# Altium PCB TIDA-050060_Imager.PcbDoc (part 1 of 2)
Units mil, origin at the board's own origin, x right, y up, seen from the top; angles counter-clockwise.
Board outline 989.05 x 988.04 mil, 6 copper layers (TOP, GND1, POWER1, INNER1, GND2, BOTTOM), stack 61.2 mil thick; 79 components, 47 nets, 342 pads, 154 vias.
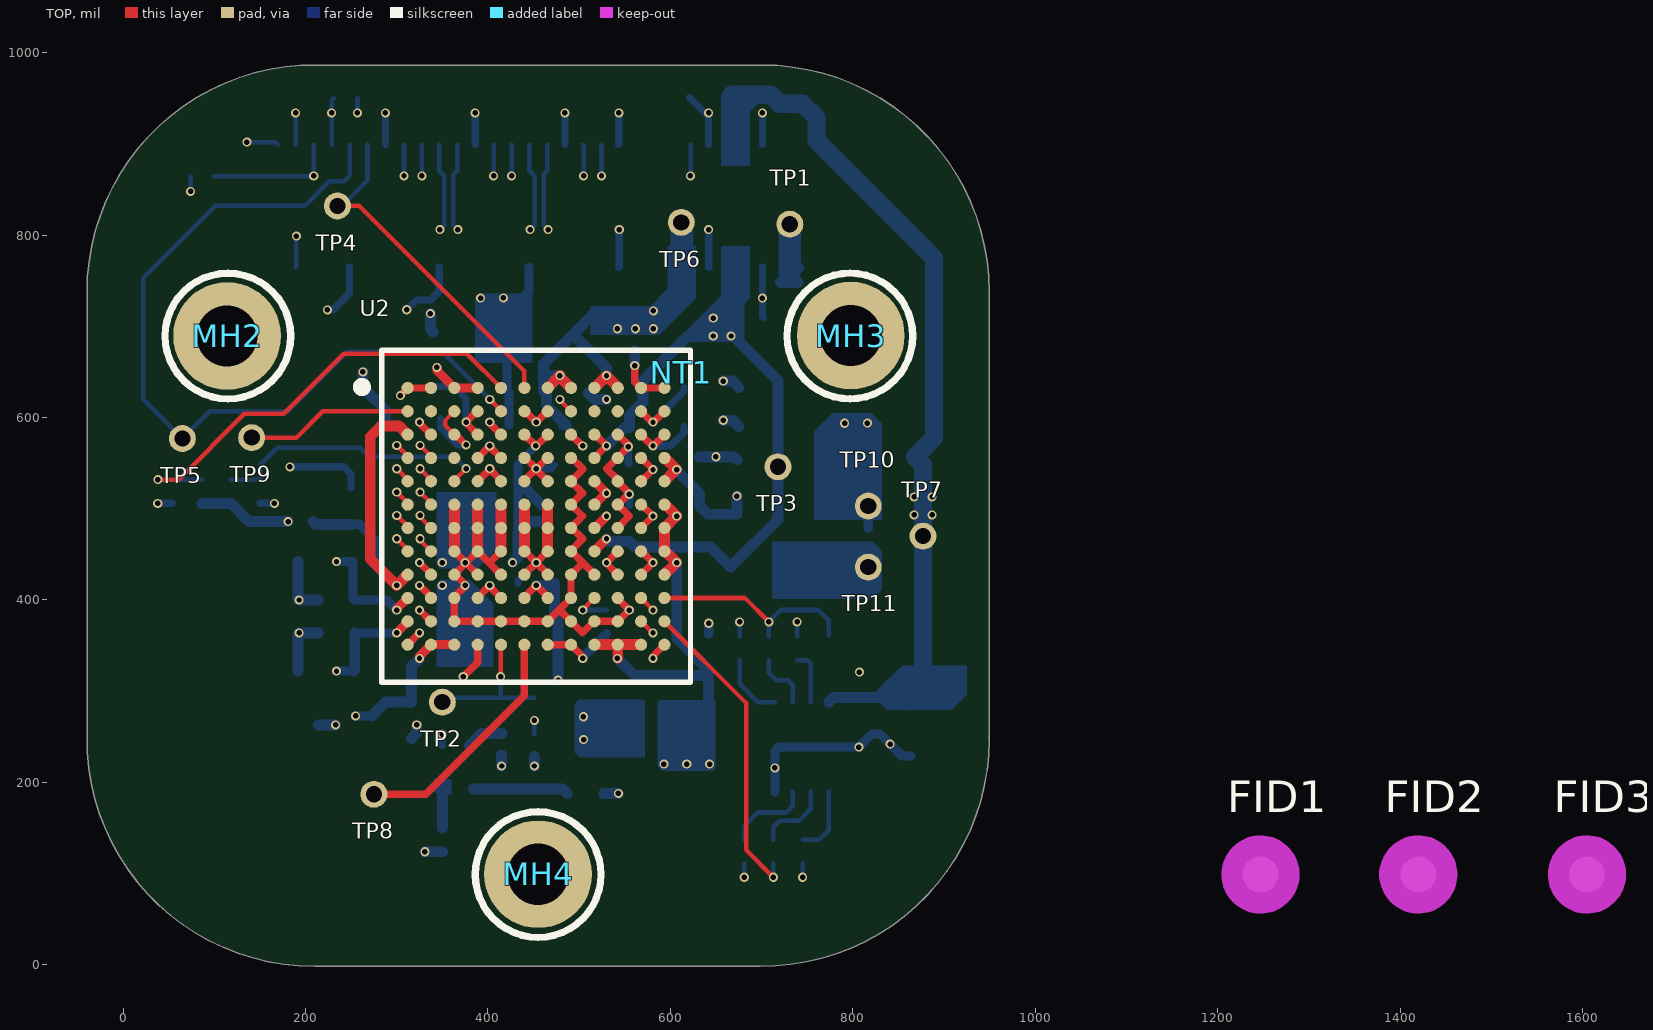
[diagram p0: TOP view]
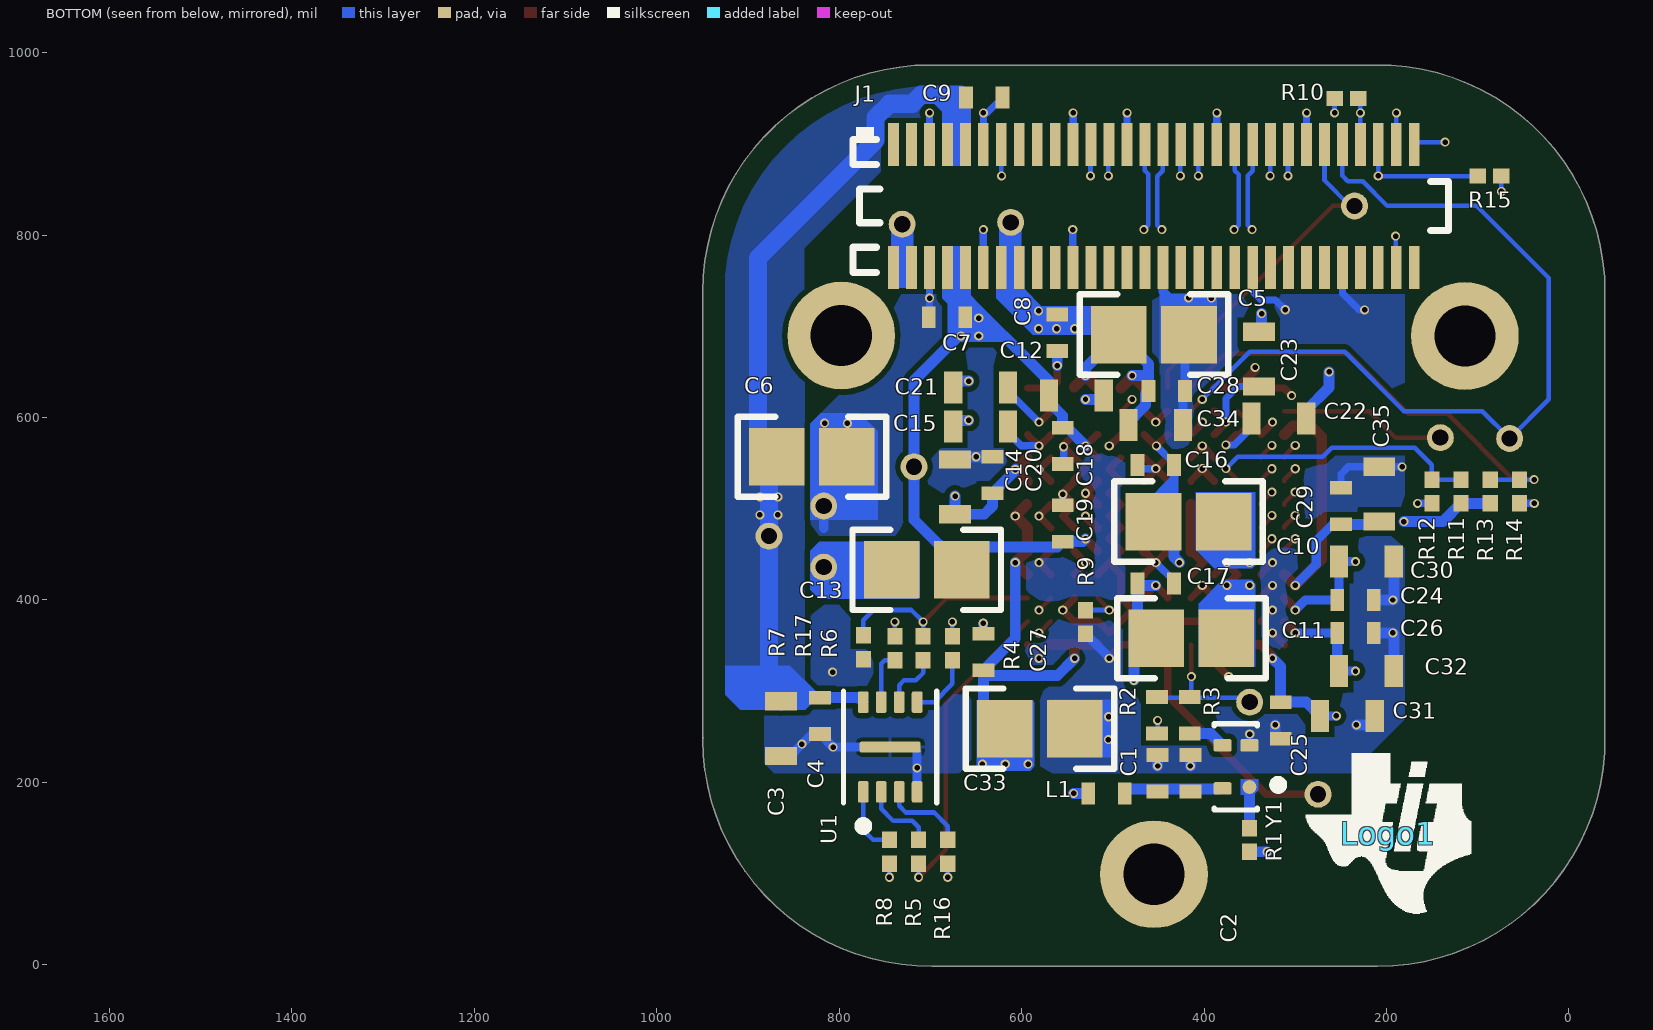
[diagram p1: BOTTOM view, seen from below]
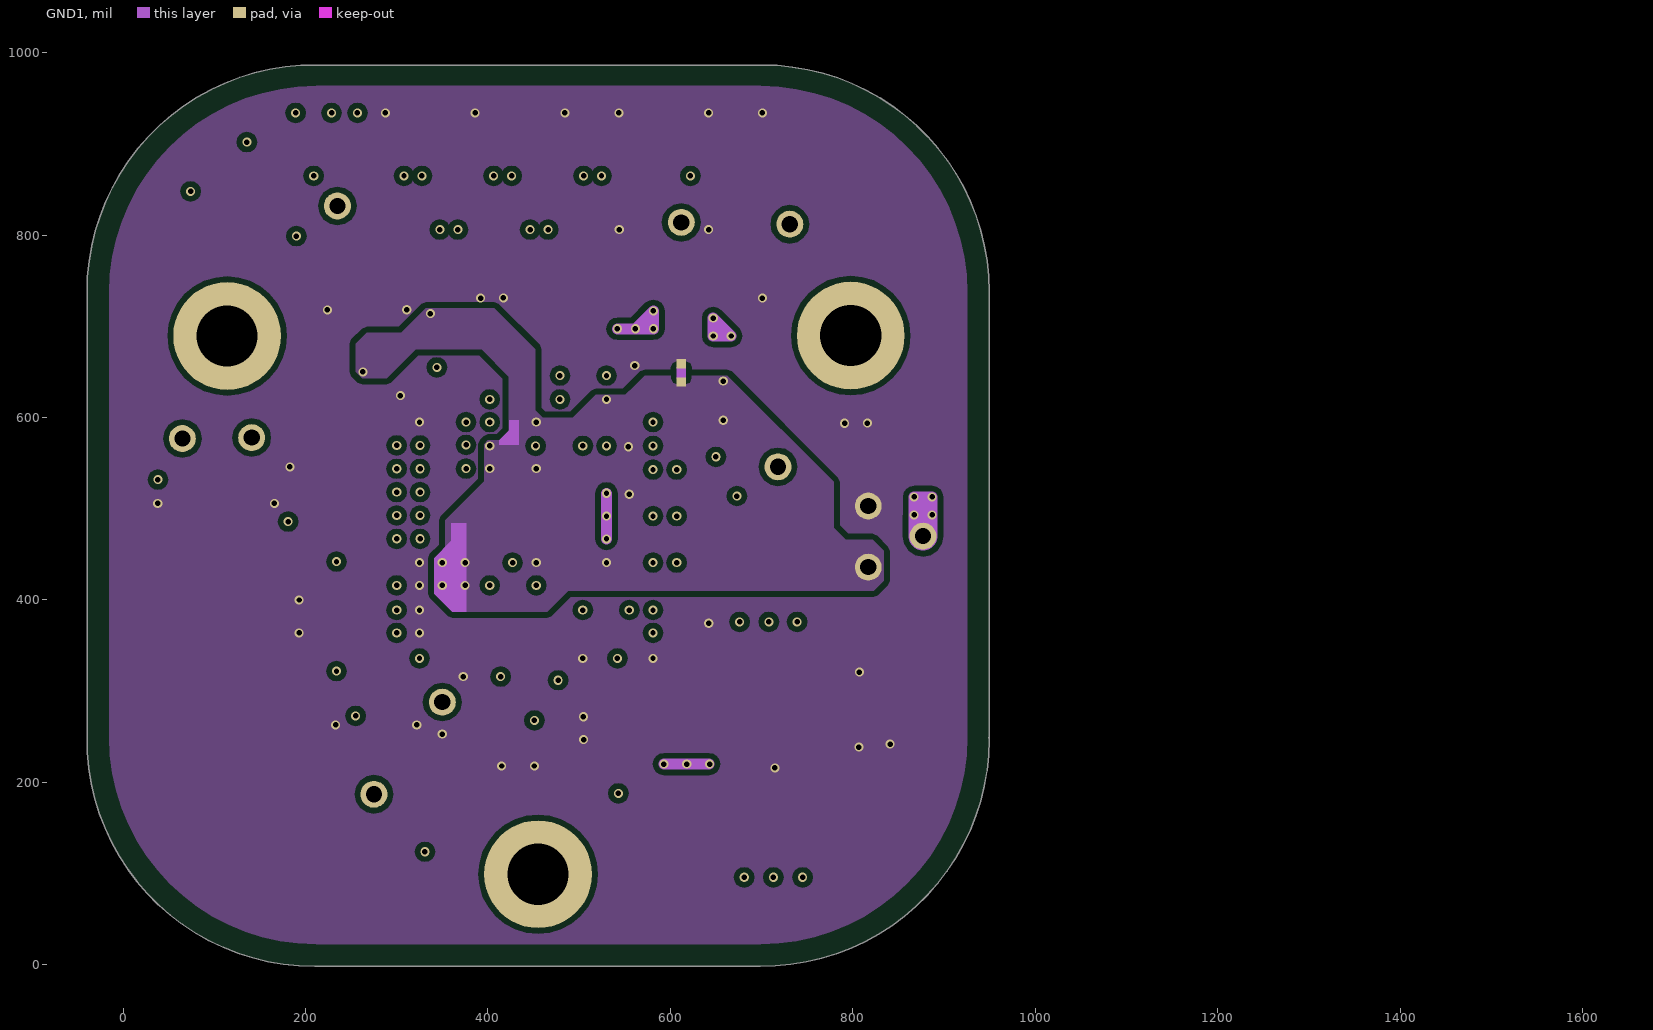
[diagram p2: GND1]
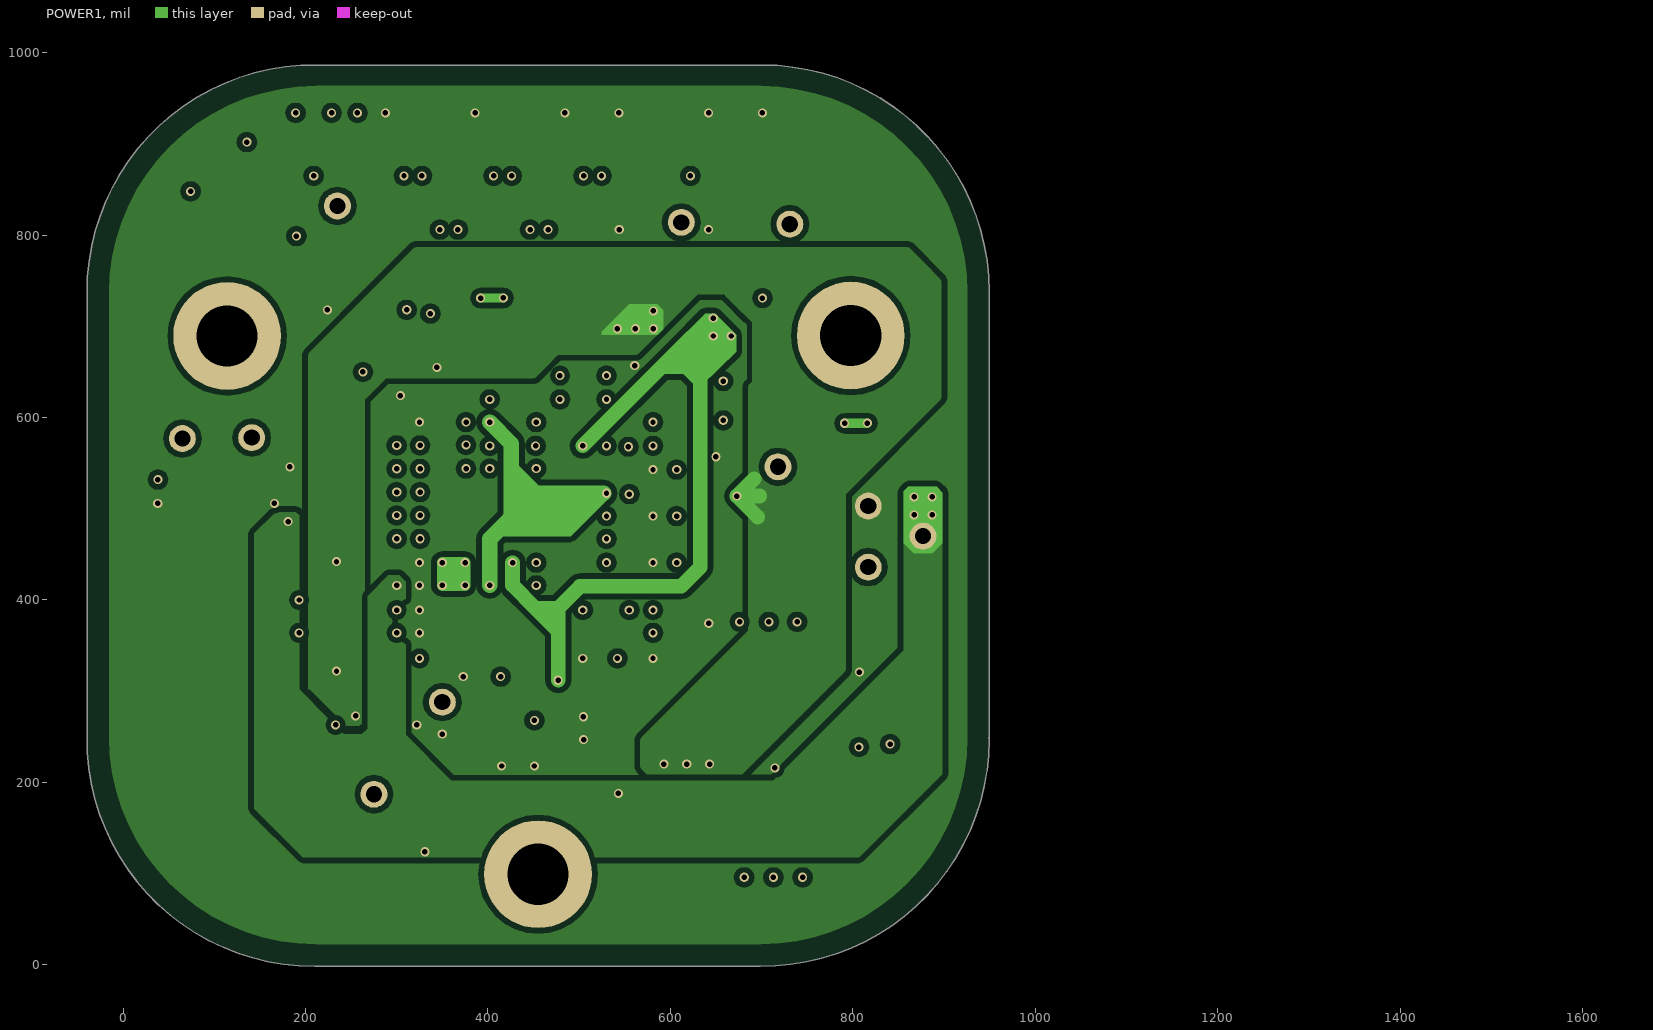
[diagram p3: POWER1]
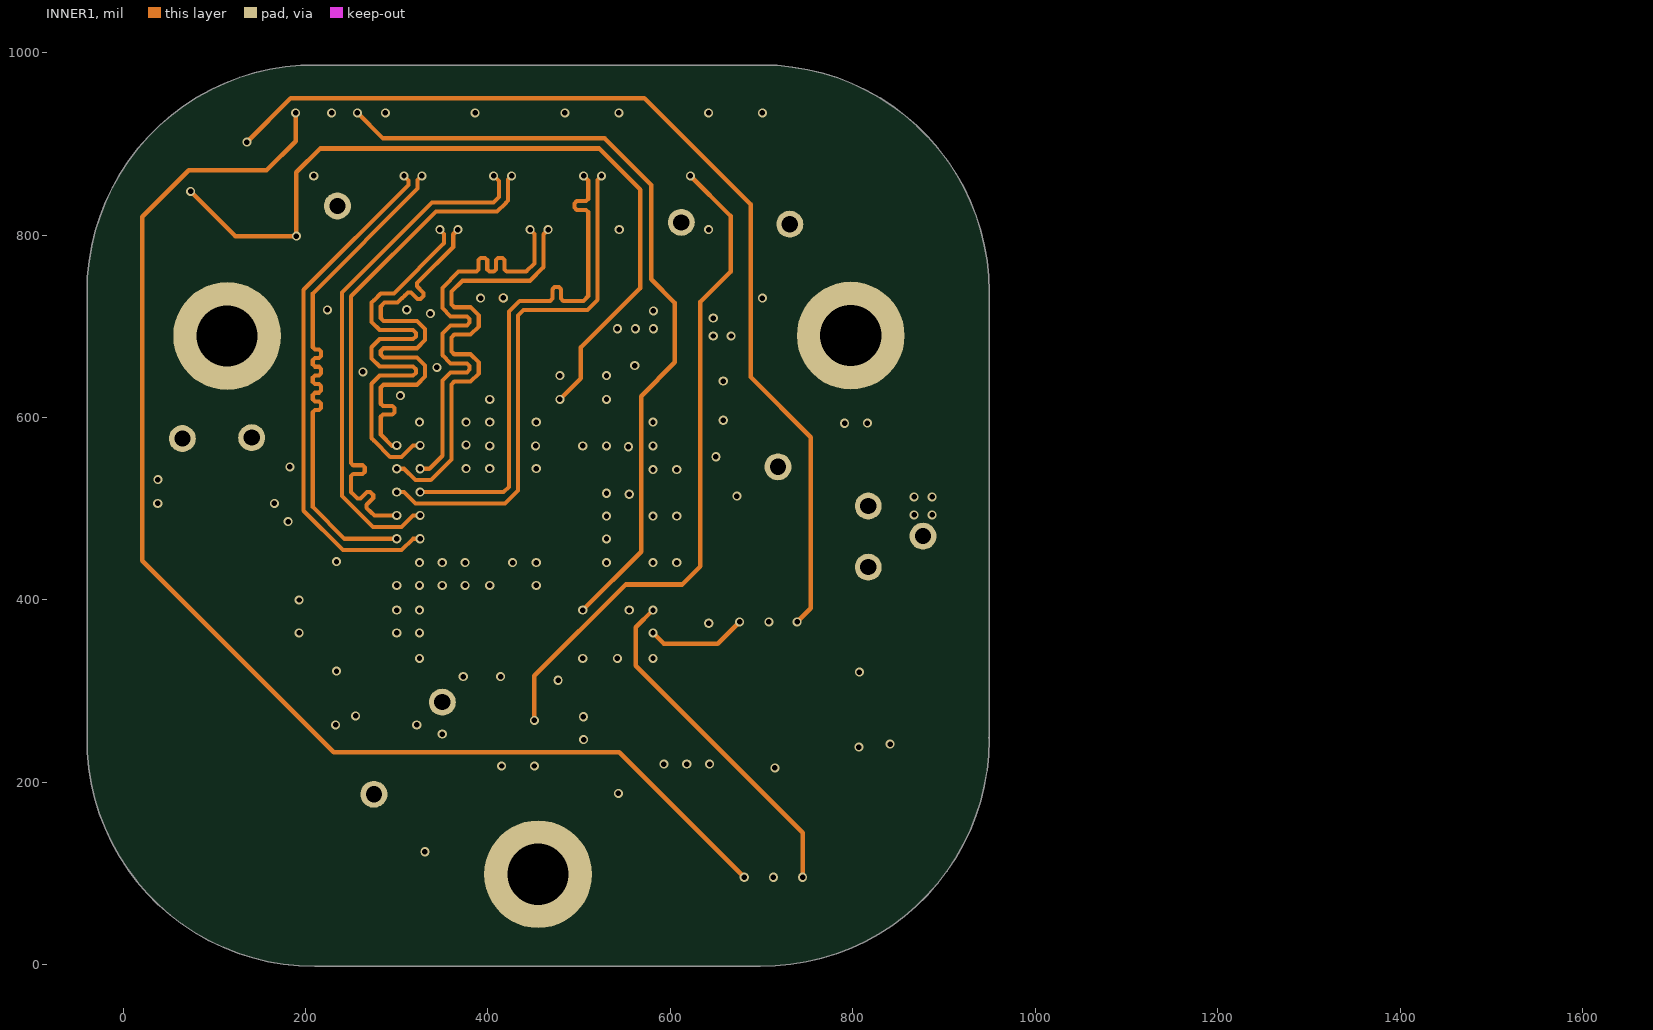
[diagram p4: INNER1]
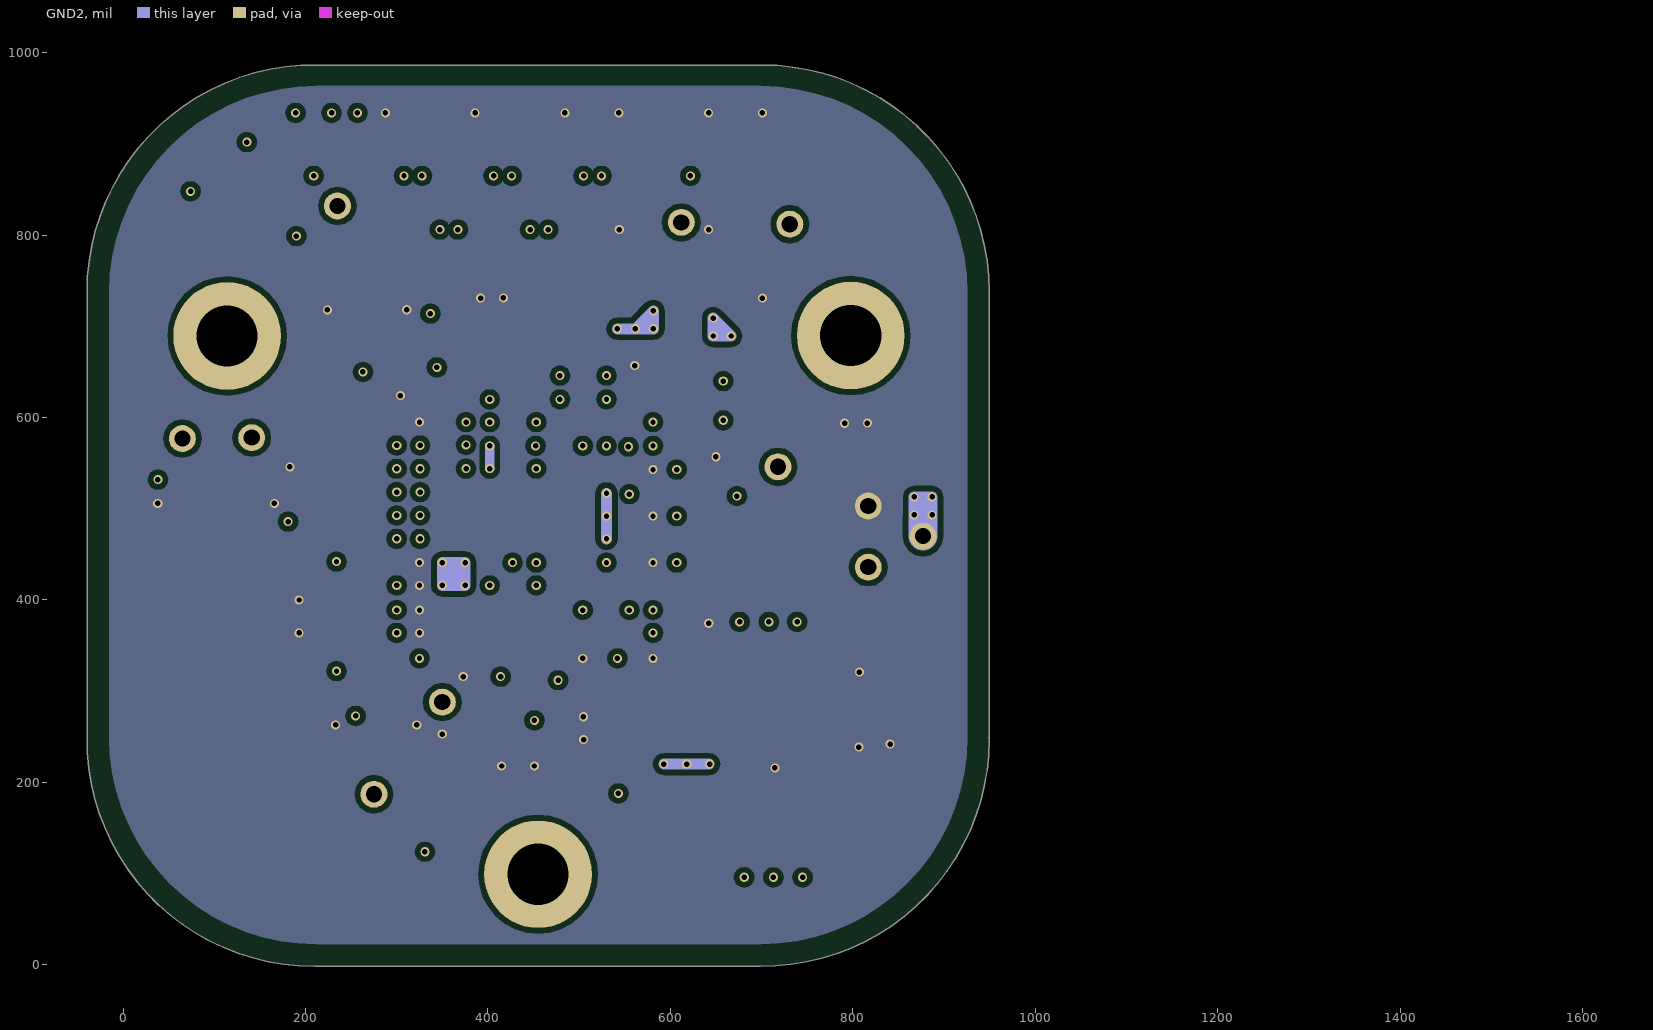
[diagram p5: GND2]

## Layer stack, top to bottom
Top Solder: solder mask 0.4, Solder Resist, Dk 3.5
TOP: signal copper 1.4
Dielectric 1: core 4, FR-4, Dk 4.3
GND1: signal copper 0.7
Dielectric2: core 6, FR-4, Dk 4.3
POWER1: signal copper 0.7
Dielectric3: core 35.6, FR-4, Dk 4.5
INNER1: signal copper 0.7
Dielectric4: core 6, FR-4, Dk 4.3
GND2: signal copper 0.7
Dielectric5: core 4, FR-4, Dk 4.3
BOTTOM: signal copper 1.4
Bottom Solder: solder mask 0.4, Solder Resist, Dk 3.5

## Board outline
210,-1.52 cw(c208.99,247) -39.51,250.01 cw(c208.99,247) -39.51,250.02 -39.51,250 -39.51,736.86 cw(c-38.01,737) -39.52,736.99 cw(c209,738) 211.85,986.51 cw(c212.01,985) 212.01,986.51 699.88,986.51 cw(c700.01,985.01) 700,986.52 cw(c701.01,738) 949.53,738 cw(c701.01,738) 949.52,734.99 949.52,250 cw(c948,250) 949.14,249 cw(c948.01,247.99) 949.52,248 cw(c701,246.99) 949.52,246.99 cw(c701,246.99) 697.99,-1.52 cw(c701,246.99) 697.98,-1.51 698,-1.52 210.12,-1.52 cw(c209.99,-0.01)

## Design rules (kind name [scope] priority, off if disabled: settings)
AcuteAngle [All] p1 off: minimum=4.50000000000000E+0001 checktracksonly=FALSE
AssemblyTestPointUsage [All] p1: valid=2
Clearance Clearance_BoardEdge_MountingHoles [OnCopper and InComponentClass('Mounting Holes') vs IsKeepOut] p1 off: gap=30 ignorepadtopadclearanceinfootprint=FALSE except(0: Arc-Hole Track-Hole SMDPad-Hole THPad-Hole Via-Hole Fill-Hole Poly-Hole Region-Hole Text-Hole)
Clearance Clearance_BoardEdge_Poly [OnCopper and InPoly vs IsKeepOut] p2: gap=15 ignorepadtopadclearanceinfootprint=FALSE except(0: Arc-Hole Track-Hole SMDPad-Hole THPad-Hole Via-Hole Fill-Hole Poly-Hole Region-Hole Text-Hole)
Clearance Clearance_BoardEdge [OnCopper and Not InComponentClass('Logo') and not InComponentClass('FiducialMark') and not InRegion(1000,500,4000,800) and Not IsKeepout vs IsKeepOut and Not OnLayer('Keep-out Layer')] p3: gap=11 ignorepadtopadclearanceinfootprint=FALSE except(0: Arc-Hole Track-Hole SMDPad-Hole THPad-Hole Via-Hole Fill-Hole Poly-Hole Region-Hole Text-Hole)
Clearance Clearance_Poly [InNamedPolygon('GND_L01_P099')] p4: gap=6 ignorepadtopadclearanceinfootprint=FALSE
Clearance Clearance_Poly_1 [InPolygon] p5: gap=6 ignorepadtopadclearanceinfootprint=FALSE
Clearance Clearance_1 [All] p6: gap=4 ignorepadtopadclearanceinfootprint=FALSE except(0: Arc-Hole Track-Hole SMDPad-Hole THPad-Hole Via-Hole Fill-Hole Poly-Hole Region-Hole Text-Hole)
ComponentClearance ComponentClearance_1 [issmtcomponent] p1: gap=0 collisioncheckmode=3 verticalgap=0 showdistances=FALSE
ComponentClearance ComponentClearance_Shunt [InComponentClass('Header') vs InComponentClass('Shunt')] p2: gap=0 collisioncheckmode=3 verticalgap=0 showdistances=FALSE
ComponentClearance ComponentClearance_Logo [InComponentClass('Logo')] p3: gap=0 collisioncheckmode=3 verticalgap=0 showdistances=FALSE
ComponentClearance ComponentClearance_ScrewToNut [(HasFootprint('NY PMS 440 0025 PH')) vs (HasFootprint('Keystone_1902C'))] p4: gap=5 collisioncheckmode=3 verticalgap=10 showdistances=FALSE
ComponentClearance ComponentClearance_MountingHoles [InComponentClass('Mounting Holes')] p5: gap=50 collisioncheckmode=3 verticalgap=50 showdistances=FALSE
ComponentClearance ComponentClearance_SmallPassives [HasFootprint('0201*') or HasFootprint('0402*') or HasFootprint('0508') or HasFootprint('0603*') or HasFootprint('0612') or HasFootprint('0805*') or HasFootprint('0815*') or HasFootprint('0830*') or HasFootprint('1206*') or HasFootprint('1210*') or HasFootprint('1808*') or HasFootprint('1812*') or HasFootprint('1825*') or HasFootprint('2010*') or HasFootprint('2220*') or HasFootprint('2225*') or HasFootprint('2512*') or HasFootprint('2728*') or HasFootprint('3518*') vs HasFootprint('0201*') or HasFootprint('0402*') or HasFootprint('0508') or HasFootprint('0603*') or HasFootprint('0612') or HasFootprint('0805*') or HasFootprint('0815*') or HasFootprint('0830*') or HasFootprint('1206*') or HasFootprint('1210*') or HasFootprint('1808*') or HasFootprint('1812*') or HasFootprint('1825*') or HasFootprint('2010*') or HasFootprint('2220*') or HasFootprint('2225*') or HasFootprint('2512*') or HasFootprint('2728*') or HasFootprint('3518*')] p6: gap=0 collisioncheckmode=3 verticalgap=0 showdistances=FALSE
ComponentClearance ComponentClearance_THtoSMT [IsThruComponent vs IsSMTComponent] p7: gap=0 collisioncheckmode=3 verticalgap=0 showdistances=FALSE
ComponentClearance ComponentClearance_THtoTH [IsThruComponent vs IsThruComponent] p8: gap=0 collisioncheckmode=3 verticalgap=0 showdistances=FALSE
ComponentClearance [All] p9: gap=0 collisioncheckmode=3 verticalgap=0 showdistances=FALSE
DiffPairsRouting DiffPair_Diff100_DiffPairsRouting [InDifferentialPairClass('Diff100')] p1: maxlimit=8 minlimit=5 mostfreqgap=8 toplayer_mingap=8 toplayer_minwidth=8 toplayer_maxwidth=8 toplayer_prefwidth=8 midlayer1_mingap=8 midlayer1_minwidth=8 midlayer1_maxwidth=8 midlayer1_prefwidth=8 midlayer2_mingap=8 midlayer2_minwidth=8 midlayer2_maxwidth=8 midlayer2_prefwidth=8 midlayer3_maxgap=5 midlayer3_prefgap=5 midlayer3_minwidth=4.5 midlayer3_maxwidth=5 midlayer3_prefwidth=5 midlayer4_maxgap=5 midlayer4_prefgap=5 midlayer4_minwidth=5 midlayer4_maxwidth=5 midlayer4_prefwidth=5 bottomlayer_mingap=8 bottomlayer_minwidth=8 bottomlayer_maxwidth=8 bottomlayer_prefwidth=8 maxuncoupledlength=500
DiffPairsRouting [All] p2: maxlimit=15 minlimit=5 mostfreqgap=8 toplayer_maxgap=5 toplayer_prefgap=5 toplayer_minwidth=5 toplayer_maxwidth=15 toplayer_prefwidth=8 midlayer1_maxgap=5 midlayer1_prefgap=5 midlayer1_minwidth=5 midlayer1_maxwidth=15 midlayer1_prefwidth=8 midlayer2_minwidth=3 midlayer2_maxwidth=10 midlayer2_prefwidth=5 midlayer3_maxgap=5 midlayer3_prefgap=5 midlayer3_minwidth=4.5 midlayer3_maxwidth=15 midlayer3_prefwidth=8 midlayer4_maxgap=5 midlayer4_prefgap=5 midlayer4_minwidth=5 midlayer4_maxwidth=15 midlayer4_prefwidth=8 bottomlayer_maxgap=5 bottomlayer_prefgap=5 bottomlayer_minwidth=5 bottomlayer_maxwidth=15 bottomlayer_prefwidth=8 maxuncoupledlength=1000
FabricationTestPointUsage TestPointUsage [All] p1: valid=2 allowmultiple=FALSE
FabricationTestpoint Testpoint [All] p1: side=3 testpointundercomponent=TRUE minsize=40 maxsize=100 preferedsize=60 minholesize=0 maxholesize=40 preferedholesize=32 testpointgrid=1 allowsidetop=TRUE allowsidebottom=TRUE usegrid=TRUE gridtolerance=0.01
FanoutControl Fanout_LCC [IsLCC] p1: bgadir=Out bgaviamode=Centered fanoutstyle=Auto fanoutdirection=Alternating viagrid=1 // Fanout_LCC (Default Rule)
FanoutControl Fanout_BGA [IsBGA] p2: bgadir=Out bgaviamode=Centered fanoutstyle=Auto fanoutdirection=Alternating viagrid=1 // Fanout_BGA (Default Rule)
FanoutControl Fanout_Default [All] p4: bgadir=Out bgaviamode=Centered fanoutstyle=Auto fanoutdirection=Alternating viagrid=1 // Fanout_Default (Default Rule)
FanoutControl Fanout_Small [(CompPinCount < 5)] p5: bgadir=Out bgaviamode=Centered fanoutstyle=Auto fanoutdirection=OutThenIn viagrid=1 // Fanout_Small (Default Rule)
HoleSize [All] p1: absolutevalues=TRUE maxlimit=280 minlimit=6 maxpercent=80.000 minpercent=20.000
MatchedLengths DiffPair_Diff100_MatchedLengths [InDifferentialPairClass('Diff100')] p1: tolerance=25 checknetsindiffpair=FALSE checkdiffpairvsdiffpair=TRUE checkxsignals=TRUE checkothers=TRUE
MinimumAnnularRing MinimumAnnularRing_ThermalPadVias [IsVia and InAnyComponent] p1: minimumring=5.91
MinimumAnnularRing [All] p2: minimumring=2
MinimumSolderMaskSliver MinimumSolderMaskSliver_Logo [InComponentClass('Logo') vs InComponentClass('Logo')] p1: minsoldermaskwidth=0.7
MinimumSolderMaskSliver [All] p2: minsoldermaskwidth=3.94
PlaneConnect [All] p1: planeconnectstyle=Relief reliefexpansion=10 reliefentries=4 reliefconductorwidth=10 reliefairgap=10
PolygonConnect PolygonConnect_1 [InComponent('U1')] p1: thpad.connectstyle=Relief thpad.reliefconductorwidth=4 thpad.reliefentries=4 thpad.polygonreliefangle="90 Angle" thpad.airgapwidth=4 smdpad.connectstyle=Relief smdpad.reliefconductorwidth=4 smdpad.reliefentries=4 smdpad.polygonreliefangle="90 Angle" smdpad.airgapwidth=4 via.connectstyle=Direct via.reliefconductorwidth=12 via.reliefentries=4 via.polygonreliefangle="90 Angle" via.airgapwidth=6
PolygonConnect PolygonConnect_2 [InComponent('U4')] p2: thpad.connectstyle=Relief thpad.reliefconductorwidth=4 thpad.reliefentries=4 thpad.polygonreliefangle="90 Angle" thpad.airgapwidth=4 smdpad.connectstyle=Relief smdpad.reliefconductorwidth=4 smdpad.reliefentries=4 smdpad.polygonreliefangle="90 Angle" smdpad.airgapwidth=4 via.connectstyle=Direct via.reliefconductorwidth=12 via.reliefentries=4 via.polygonreliefangle="90 Angle" via.airgapwidth=6
PolygonConnect [All] p3: connectstyle=Direct reliefconductorwidth=12 reliefentries=4 polygonreliefangle="90 Angle" airgapwidth=6
RoutingVias ThermalPadVias [IsVia and InAnyComponent] p1: holewidth=7.87 width=19.68 viastyle="Through Hole" minholewidth=7.87 minwidth=19.68 maxholewidth=12.99 maxwidth=23.62
RoutingVias [All] p2: holewidth=10 width=22 viastyle="Through Hole" minholewidth=6 minwidth=10 maxholewidth=40 maxwidth=65
SMDToCorner [All] p1: distance=25000
SilkToBoardRegionClearance [Not ((IsComment or IsDesignator) And (Hide <> 'False')) and not InRegion(1000,500,4000,800)] p1:
SilkToSilkClearance [All] p1: silktosilkclearance=0
SilkToSolderMaskClearance SilkscreenOverComponentPads [IsPad] p1: minsilkscreentomaskgap=0.2 clearancetoexposedcopper=TRUE
SolderMaskExpansion [All] p1: expansion=1 istentingtop=FALSE
Width [All] p1: maxlimit=100 minlimit=5 preferedwidth=10 minimp=50.000000 maximp=50.000000 favimp=50.000000 checkconnectedcopper=TRUE
15 further rules are at their usual default settings.

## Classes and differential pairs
component class TIDA-050060_Imager: C1 C2 C3 C4 C5 C6 C7 C8 C9 C10 C11 C12 C13 C14 C15 C16 C17 C18 C19 C20 C21 C22 C23 C24 C25 C26 C27 C28 C29 C30 C31 C32 C33 C34 C35 J1 L1 NT1 R1 R2 R3 R4 R5 R6 R7 R8 R9 R10 R11 R12 R13 R14 R15 R16 R17 TP1 TP2 TP3 TP4 TP5 TP6 TP7 TP8 TP9 TP10 TP11 U1 U2 Y1
component class Logo: Logo1
component class TIDA-050060_Hardware: FID1 FID2 FID3 Logo1 ZZ1 ZZ2 ZZ3
component class FiducialMark: FID1 FID2 FID3
component class AssemblyNote: ZZ1 ZZ2 ZZ3
differential pair CSI2_D3: +CSI2_D3_P -CSI2_D3_N
differential pair CSI2_D2: +CSI2_D2_P -CSI2_D2_N
differential pair CSI2_D1: +CSI2_D1_P -CSI2_D1_N
differential pair CSI2_D0: +CSI2_D0_P -CSI2_D0_N
differential pair CSI2_CK: +CSI2_CK_P -CSI2_CK_N

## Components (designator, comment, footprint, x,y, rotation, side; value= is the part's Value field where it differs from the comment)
C1 "GCM155R71C104KA55D" 0402S 451,210 r90 bottom value=0.1uF
C2 "CGA2B3X7R1H103K050BB" 0402S 415,210 r90 bottom value=0.01uF
C3 "GCM188R71C105KA64J" 0603S 864,259 r270 bottom value=1uF
C4 "GCM155R71C104KA55D" 0402S 821,273 r270 bottom value=0.1uF
C5 "GCM21BR71A106KE22L" 0805M 455,691 r180 bottom value=10uF
C6 "GCM21BR71A106KE22L" 0805M 830,557 r180 bottom value=10uF
C7 "GCM155R71C104KA55D" 0402S 682,710 r0 bottom value=0.1uF
C8 "GCM155R71C104KA55D" 0402S 561,693 r270 bottom value=0.1uF
C9 "GCM155R71C104KA55D" 0402S 641,951 r180 bottom value=0.1uF
C10 "CGA4J3X7R1C475K125AE" 0805M 417,486 r180 bottom value=4.7uF
C11 "CGA4J3X7R1C475K125AE" 0805M 414,358 r180 bottom value=4.7uF
C12 "GCM188R71C105KA64J" 0603S 540,624 r180 bottom value=1uF
C13 "CGA4J3X7R1C475K125AE" 0805M 704,433 r0 bottom value=4.7uF
C14 "GCM188R71C105KA64J" 0603S 673,524 r90 bottom value=1uF
C15 "GCM188R70J225KE22D" 0603S 645,590 r0 bottom value=2.2uF
C16 "GCM155R71C104KA55D" 0402S 453,548 r0 bottom value=0.1uF
C17 "GCM155R71C104KA55D" 0402S 453,418 r180 bottom value=0.1uF
C18 "GCM155R71C104KA55D" 0402S 555,569 r270 bottom value=0.1uF
C19 "GCM155R71C104KA55D" 0402S 555,484 r90 bottom value=0.1uF
C20 "GCM155R71C104KA55D" 0402S 632,537 r90 bottom value=0.1uF
C21 "GCM188R70J225KE22D" 0603S 645,633 r0 bottom value=2.2uF
C22 "GCM188R71C105KA64J" 0603S 318,599 r180 bottom value=1uF
C23 "GCM188R71C105KA64J" 0603S 340,664 r90 bottom value=1uF
C24 "GCM155R71C104KA55D" 0402S 234,400 r180 bottom value=0.1uF
C25 "GCM155R71C104KA55D" 0402S 316,268 r270 bottom value=0.1uF
C26 "GCM155R71C104KA55D" 0402S 234,364 r180 bottom value=0.1uF
C27 "GCM155R71C104KA55D" 0402S 642,343 r90 bottom value=0.1uF
C28 "GCM155R71C104KA55D" 0402S 441,629 r180 bottom value=0.1uF
C29 "GCM155R71C104KA55D" 0402S 250,503 r90 bottom value=0.1uF
C30 "GCM188R71C105KA64J" 0603S 222,442 r180 bottom value=1uF
C31 "GCM188R71C105KA64J" 0603S 243,273 r180 bottom value=1uF
C32 "GCM188R71C105KA64J" 0603S 222,322 r180 bottom value=1uF
C33 "CGA4J3X7R1C475K125AE" 0805M 580,259 r180 bottom value=4.7uF
C34 "GCM188R71C105KA64J" 0603S 453,592 r180 bottom value=1uF
C35 "GCM188R71C105KA64J" 0603S 208,516 r90 bottom value=1uF
FID1 "Fiducial" Fiducial10-20 1247,99 r0 top
FID2 "Fiducial" Fiducial10-20 1420,99 r0 top
FID3 "Fiducial" Fiducial10-20 1605,99 r0 top
J1 "ST5-30-1.50-L-D-P-TR" Samtec_ST5-30-1_50-x-D-P 455,832 r180 bottom
L1 "BLM15AG221SN1D" 0402S 507,188 r180 bottom value="220 ohm"
Logo1 "Texas Instruments" TI_Symbol_Overlay_Small 198,144 r180 bottom
MH2 "MOUNT_HOLE_1_MTG170_300_MOUNT H" MTG170_300#1 115,689.37 r0 top
MH3 "MOUNT_HOLE_1_MTG170_300_MOUNT H" MTG170_300#2 796.9,689.44 r0 top
MH4 "MOUNT_HOLE_1_MTG170_300_MOUNT H" MTG170_300#3 455,99 r0 top
NT1 "Net-Tie" Net-Tie_10mil 612,649 r270 top net-tie
R1 "RC0201JR-074K7L" 0201 350,137 r270 bottom value=4.7k
R2 "ERJ-2GE0R00X" 0402S 451.71,273.64 r90 bottom value=0
R3 "ERJ-2GEJ220X" 0402S 415.71,273.64 r90 bottom value=22
R4 "ERJ-1GE0R00C" 0201 676,347.01 r90 bottom value=0
R5 "ERJ-1GE0R00C" 0201 713,124.01 r270 bottom value=0
R6 "ERJ-1GE0R00C" 0201 708,347.01 r90 bottom value=0
R7 "RC0201JR-074K7L" 0201 773.5,348.24 r90 bottom value=4.7k
R8 "ERJ-1GE0R00C" 0201 745,124.01 r90 bottom value=0
R9 "RC0201JR-074K7L" 0201 530,376 r90 bottom value=4.7k
R10 "ERJ-1GE0R00C" 0201 244,950 r180 bottom value=0
R11 "RC0201JR-074K7L" 0201 118.25,519.01 r270 bottom value=4.7k
R12 "RC0201JR-074K7L" 0201 150.25,519.01 r90 bottom value=4.7k
R13 "RC0201JR-074K7L" 0201 86.25,518.99 r270 bottom value=4.7k
R14 "RC0201JR-074K7L" 0201 54.25,518.99 r90 bottom value=4.7k
R15 "ERJ-1GE0R00C" 0201 87,864.7 r180 bottom value=0
R16 "ERJ-1GE0R00C" 0201 681,124.01 r90 bottom value=0
R17 "ERJ-1GE0R00C" 0201 739,347.01 r270 bottom value=0
TP1 "TP_H0.45P0.75" TP_H045P075 731,812 r180 top
TP2 "TP_H0.45P0.75" TP_H045P075 350,288 r90 top
TP3 "TP_H0.45P0.75" TP_H045P075 718,546 r180 top
TP4 "TP_H0.45P0.75" TP_H045P075 235,832 r90 top
TP5 "TP_H0.45P0.75" TP_H045P075 65,577 r90 top
TP6 "TP_H0.45P0.75" TP_H045P075 612,814 r180 top
TP7 "TP_H0.45P0.75" TP_H045P075 877,470 r180 top
TP8 "TP_H0.45P0.75" TP_H045P075 275,187 r90 top
TP9 "TP_H0.45P0.75" TP_H045P075 141,578 r90 top
TP10 "TP_H0.45P0.75" TP_H045P075 817,503 r90 top
TP11 "TP_H0.45P0.75" TP_H045P075 817,436 r90 top
U1 "W25Q40EWUXJE" FP-W25Q40EWUXJE_USON8-MFG 744.16,238.79 r90 bottom
U2 "IMX623-AAQV-W" FP-IMX623-AAQV-W_BGA144-IPC_C 452.76,491.76 r0 top
Y1 "DSC6101HA3B-024.0000" FP-DSC6101HA3B-024.0000_VFLGA4-MFG 365,217 r90 bottom
ZZ1 "These assemblies are ESD sensitive, ESD precautions shall be observed." AssemblyNote 185,3829.11 r180 bottom
ZZ2 "These assemblies must be clean and free from flux and all contaminants. Use of no clean flux is not acceptable." AssemblyNote 185,3740.56 r180 bottom
ZZ3 "These assemblies must comply with workmanship standards IPC-A-610 Class 2, unless otherwise specified." AssemblyNote 185,3652 r180 bottom

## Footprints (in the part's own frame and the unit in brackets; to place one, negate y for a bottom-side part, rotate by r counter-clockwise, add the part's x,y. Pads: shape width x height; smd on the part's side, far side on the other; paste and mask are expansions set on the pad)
0201 [mm] "Data from Kemet datasheet CC101_COM dated 7/28/11"
  rect 0.46x0.42 smd mask+0.048: 1(-0.33,0) 2(0.33,0)
  body extent -0.31,-0.16 0.31,0.16, height 0.26
0402S [mil] "Based on C0402S footprint from PADS legacy"
  rect 15x24 smd: 1(-20,0) 2(20,0)
  body extent -22,-12 22,12, height 24
0603S [mil]
  rect 20x35 smd: 1(-30,0) 2(30,0)
  body extent -34,-19 34,19, height 39
0805M [mm] "0805 from SM-752 data"
  rect 1.55x1.6 smd: 1(-0.975,0) 2(0.975,0)
  silkscreen extent -2.07,-1.12 2.07,1.12, body extent -1.1,-0.72 1.1,0.72, height 1.45
AssemblyNote [mil] "Assembly Note"
Fiducial10-20 [mm]
  round 1 smd mask+0.5: 1(0,0)
  TOP keep-out circle w1.178: c0,0 r0.5
FP-DSC6101HA3B-024.0000_VFLGA4-MFG [mm]
  round 0.387 smd paste+0 mask+0: 1(-0.56,-0.375)
  rrect29% 0.35x0.5 smd paste+0 mask+0: 2(0.6,-0.375) 3(0.6,0.375) 4(-0.6,0.375)
  TOP region: -0.775,-0.125 -0.345,-0.125 -0.345,-0.625 -0.645,-0.625 -0.775,-0.495
  silkscreen extent -1.2,-1.3 1.2,0.6, body extent -0.8,-0.6 0.8,0.6, height 0.89
FP-IMX623-AAQV-W_BGA144-IPC_C [mm]
  round 0.34 smd paste+0 mask+0: A1(-3.575,3.575) A2(-2.925,3.575) A3(-2.275,3.575) A4(-1.625,3.575) A5(-0.975,3.575) A6(-0.325,3.575) A7(0.325,3.575) A8(0.975,3.575) A9(1.625,3.575) A10(2.275,3.575) A11(2.925,3.575) A12(3.575,3.575) B1(-3.575,2.925) B2(-2.925,2.925) B3(-2.275,2.925) B4(-1.625,2.925) B5(-0.975,2.925) B6(-0.325,2.925) B7(0.325,2.925) B8(0.975,2.925) B9(1.625,2.925) B10(2.275,2.925) B11(2.925,2.925) B12(3.575,2.925) C1(-3.575,2.275) C2(-2.925,2.275) C3(-2.275,2.275) C4(-1.625,2.275) C5(-0.975,2.275) C6(-0.325,2.275) C7(0.325,2.275) C8(0.975,2.275) C9(1.625,2.275) C10(2.275,2.275) C11(2.925,2.275) C12(3.575,2.275) D1(-3.575,1.625) D2(-2.925,1.625) D3(-2.275,1.625) D4(-1.625,1.625) D5(-0.975,1.625) D6(-0.325,1.625) D7(0.325,1.625) D8(0.975,1.625) D9(1.625,1.625) D10(2.275,1.625) D11(2.925,1.625) D12(3.575,1.625) E1(-3.575,0.975) E2(-2.925,0.975) E3(-2.275,0.975) E4(-1.625,0.975) E5(-0.975,0.975) E6(-0.325,0.975) E7(0.325,0.975) E8(0.975,0.975) E9(1.625,0.975) E10(2.275,0.975) E11(2.925,0.975) E12(3.575,0.975) F1(-3.575,0.325) F2(-2.925,0.325) F3(-2.275,0.325) F4(-1.625,0.325) F5(-0.975,0.325) F6(-0.325,0.325) F7(0.325,0.325) F8(0.975,0.325) F9(1.625,0.325) F10(2.275,0.325) F11(2.925,0.325) F12(3.575,0.325) G1(-3.575,-0.325) G2(-2.925,-0.325) G3(-2.275,-0.325) G4(-1.625,-0.325) G5(-0.975,-0.325) G6(-0.325,-0.325) G7(0.325,-0.325) G8(0.975,-0.325) G9(1.625,-0.325) G10(2.275,-0.325) G11(2.925,-0.325) G12(3.575,-0.325) H1(-3.575,-0.975) H2(-2.925,-0.975) H3(-2.275,-0.975) H4(-1.625,-0.975) H5(-0.975,-0.975) H6(-0.325,-0.975) H7(0.325,-0.975) H8(0.975,-0.975) H9(1.625,-0.975) H10(2.275,-0.975) H11(2.925,-0.975) H12(3.575,-0.975) J1(-3.575,-1.625) J2(-2.925,-1.625) J3(-2.275,-1.625) J4(-1.625,-1.625) J5(-0.975,-1.625) J6(-0.325,-1.625) J7(0.325,-1.625) J8(0.975,-1.625) J9(1.625,-1.625) J10(2.275,-1.625) J11(2.925,-1.625) J12(3.575,-1.625) K1(-3.575,-2.275) K2(-2.925,-2.275) K3(-2.275,-2.275) K4(-1.625,-2.275) K5(-0.975,-2.275) K6(-0.325,-2.275) K7(0.325,-2.275) K8(0.975,-2.275) K9(1.625,-2.275) K10(2.275,-2.275) K11(2.925,-2.275) K12(3.575,-2.275) L1(-3.575,-2.925) L2(-2.925,-2.925) L3(-2.275,-2.925) L4(-1.625,-2.925) L5(-0.975,-2.925) L6(-0.325,-2.925) L7(0.325,-2.925) L8(0.975,-2.925) L9(1.625,-2.925) L10(2.275,-2.925) L11(2.925,-2.925) L12(3.575,-2.925) M1(-3.575,-3.575) M2(-2.925,-3.575) M3(-2.275,-3.575) M4(-1.625,-3.575) M5(-0.975,-3.575) M6(-0.325,-3.575) M7(0.325,-3.575) M8(0.975,-3.575) M9(1.625,-3.575) M10(2.275,-3.575) M11(2.925,-3.575) M12(3.575,-3.575)
  silkscreen extent -4.97,-4.62 4.3,4.62, body extent -4.4,-4.72 4.4,4.72, height 0.25
FP-W25Q40EWUXJE_USON8-MFG [mm]
  rrect33% 0.6x0.3 smd paste-1000 mask-1000: 1(-1.25,0.75) 2(-1.25,0.25) 3(-1.25,-0.25) 4(-1.25,-0.75) 5(1.25,-0.75) 6(1.25,-0.25) 7(1.25,0.25) 8(1.25,0.75)
  rrect33% 0.3x1.7 smd paste-1000 mask+0: 9(0,0)
  silkscreen extent -2.32,-1.3 1.55,1.3, body extent -1.5,-1 1.5,1, height 0.6
MTG170_300#1 [mm] "MTG170_300"
  round 3 hole 1.7: 1(-0.023,0.002)
  silkscreen extent -1.75,-1.75 1.75,1.75, body extent -1.76,-1.76 1.76,1.76, height 3.81
MTG170_300#2 [mm] "MTG170_300"
  round 3 hole 1.7: 1(0.023,0.011)
  silkscreen extent -1.75,-1.75 1.75,1.75, body extent -1.76,-1.76 1.76,1.76, height 3.81
MTG170_300#3 [mm] "MTG170_300"
  round 3 hole 1.7: 1(0,0.009)
  silkscreen extent -1.75,-1.75 1.75,1.75, body extent -1.76,-1.76 1.76,1.76, height 3.81
Net-Tie_10mil [mil] "10mil net tie, no solder mask opening, no solder paste"
  rect 10x10 on Mid1 paste-5 mask-5: 1(-10,0) 2(10,0)
  GND1 region: -6,5 6,5 6,-5 -6,-5
Samtec_ST5-30-1_50-x-D-P [mm] "Header(unshrouded), 0.5mm, 30x2, Tin, SMT"
  rect 0.3x1.2 smd: 1(-7.25,1.71) 2(-7.25,-1.71) 3(-6.75,1.71) 4(-6.75,-1.71) 5(-6.25,1.71) 6(-6.25,-1.71) 7(-5.75,1.71) 8(-5.75,-1.71) 9(-5.25,1.71) 10(-5.25,-1.71) 11(-4.75,1.71) 12(-4.75,-1.71) 13(-4.25,1.71) 14(-4.25,-1.71) 15(-3.75,1.71) 16(-3.75,-1.71) 17(-3.25,1.71) 18(-3.25,-1.71) 19(-2.75,1.71) 20(-2.75,-1.71) 21(-2.25,1.71) 22(-2.25,-1.71) 23(-1.75,1.71) 24(-1.75,-1.71) 25(-1.25,1.71) 26(-1.25,-1.71) 27(-0.75,1.71) 28(-0.75,-1.71) 29(-0.25,1.71) 30(-0.25,-1.71) 31(0.25,1.71) 32(0.25,-1.71) 33(0.75,1.71) 34(0.75,-1.71) 35(1.25,1.71) 36(1.25,-1.71) 37(1.75,1.71) 38(1.75,-1.71) 39(2.25,1.71) 40(2.25,-1.71) 41(2.75,1.71) 42(2.75,-1.71) 43(3.25,1.71) 44(3.25,-1.71) 45(3.75,1.71) 46(3.75,-1.71) 47(4.25,1.71) 48(4.25,-1.71) 49(4.75,1.71) 50(4.75,-1.71) 51(5.25,1.71) 52(5.25,-1.71) 53(5.75,1.71) 54(5.75,-1.71) 55(6.25,1.71) 56(6.25,-1.71) 57(6.75,1.71) 58(6.75,-1.71) 59(7.25,1.71) 60(7.25,-1.71)
  silkscreen extent -8.38,-1.85 8.2,2.2, body extent -8.38,-2 8.2,2, height 4.08
TI_Symbol_Overlay_Small [mil]
  silkscreen extent -90,-88 91,88
TP_H045P075 [mm] "TP_H0.45P0.75"
  round 0.75 hole 0.45: 1(0,0)

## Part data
C1 C4 C7 C8 C9 C16 C17 C18 C19 C20 C24 C25 C26 C27 C28 C29: library part CMP-0006351-2, "CAP, CERM, 0.1 uF, 16 V, +/- 10%, X7R, 0402", Cap_Case=0402, Manufacturer=MuRata, Supplier Part Number 1=490-4759-2-ND, TempCo=X7R, Tolerance_%=10%, Value1=Unknown, Value2=16V, ValueDisplayed=0.1uF
C2: library part CMP-0006324-2, "CAP, CERM, 0.01 uF, 50 V, +/- 10%, X7R, AEC-Q200 Grade 1, 0402", Cap_Case=0402, Manufacturer=TDK, Supplier Part Number 1=445-6893-1-ND, TempCo=X7R, Tolerance_%=10%, Value1="0.333065 ohm", Value2=50V, ValueDisplayed=0.01uF
C3 C12 C14 C22 C23 C30 C31 C32 C34 C35: library part CMP-0079154-1, "CAP, CERM, 1 µF, 16 V,+/- 10%, X7R, AEC-Q200 Grade 1, 0603", Cap_Case=0603, Manufacturer=MuRata, Supplier Part Number 1=490-12657-1-ND, TempCo=X7R, Tolerance_%=10%, Value2=16V, ValueDisplayed=1µF
C5 C6: library part CMP-0008017-2, "CAP, CERM, 10 uF, 10 V, +/- 10%, X7R, 0805", Cap_Case=0805, Manufacturer=MuRata, Supplier Part Number 1=490-10674-1-ND, TempCo=X7R, Tolerance_%=10%, Value1=Unknown, Value2=10V, ValueDisplayed=10uF
C10 C11 C13 C33: library part CMP-0080701-1, "CAP, CERM, 4.7 µF, 16 V,+/- 10%, X7R, AEC-Q200 Grade 1, 0805", Cap_Case=0805, Manufacturer=TDK, Supplier Part Number 1=445-8788-1-ND, TempCo=X7R, Tolerance_%=10%, Value2=16V, ValueDisplayed=4.7µF
C15 C21: library part CMP-0007134-5, "CAP, CERM, 2.2 uF, 6.3 V, +/- 10%, X7R, AEC-Q200 Grade 1, 0603", Cap_Case=0603, Manufacturer=MuRata, Supplier Part Number 1=490-5316-1-ND, TempCo=X7R, Tolerance_%=10%, Value1=Unknown, Value2=6.3V, ValueDisplayed=2.2uF
FID1 FID2 FID3: library part CMP-0077181-1, "Fiducial mark.  There is nothing to buy or mount.", Manufacturer=N/A
J1: library part CMP-0055622-1, "Header(unshrouded), 0.5mm, 30x2, Gold, SMT", Color=Black, Current_A=1.5A, Manufacturer=Samtec
L1: library part CMP-0003312-1, "Ferrite Bead, 220 ohm @ 100 MHz, 0.45 A, 0402", Manufacturer=MuRata, Supplier Part Number 1=490-5178-1-ND, Value1="0.29 ohm", Value2=0.45A, ValueDisplayed="220 ohm"
Logo1: library part CMP-0074838-1, "Texas Instrument Corporate Signature"
NT1: library part CMP-0078142-4, "Single point connection between nets.", Manufacturer=N/A
R1 R7 R9 R11 R12 R13 R14: library part CMP-0027131-1, "RES, 4.7 k, 5%, 0.05 W, 0201", Manufacturer="Yageo America", Power_W=50mW, Supplier Part Number 1=311-4.7KNCT-ND, TempCo="200 ppm/C", Tolerance_%=5%, Value2=0.05W, Value_Code=4k70, ValueDisplayed=4.7k
R2: library part CMP-0026992-3, "RES, 0, 5%, 0.1 W, AEC-Q200 Grade 0, 0402", Manufacturer=Panasonic, Power_W=100mW, Supplier Part Number 1=P0.0JCT-ND, TempCo="600 ppm/C", Tolerance_%=5%, Value2=0.1W, Value_Code=0000, ValueDisplayed=0
R3: library part CMP-0026997-2, "RES, 22, 5%, 0.1 W, AEC-Q200 Grade 0, 0402", Manufacturer=Panasonic, Power_W=100mW, Supplier Part Number 1=P22JCT-ND, TempCo="200 ppm/C", Tolerance_%=5%, Value2=0.1W, Value_Code=22R0, ValueDisplayed=22
R4 R5 R6 R8 R10 R15 R16 R17: library part CMP-0027011-4, "RES, 0, 5%, 0.05 W, AEC-Q200 Grade 1, 0201", Manufacturer=Panasonic, Power_W=50mW, Supplier Part Number 1=P0.0AGCT-ND, TempCo="600 ppm/C", Tolerance_%=5%, Value2=0.05W, Value_Code=0000, ValueDisplayed=0
TP1 TP2 TP3 TP4 TP5 TP6 TP7 TP8 TP9 TP10 TP11: library part CMP-0003719-1, "Testpoint", Manufacturer="Texas Instruments"
U1: library part CMP-0094008-1, "W (4M-bit) Serial Flash memory, Dual/Quad SPI (XIP), USON2x3mm", Manufacturer=Winbond, Max Supply Voltage=1.95V, Min Supply Voltage=1.65V, Nominal Supply Current=1-15mA, Operating Temperature Range="-40°C to +105°C"
U2: library part CMP-0093994-1, "Diagonal 7.45mm (Type 1/2.42) CMOS Solid-State Image Sensor with Square Pixel and RGGB Filter Array", Manufacturer=Sony, Max Supply Voltage=3.465V, Min Supply Voltage=1V, Operating Temperature Range="-40°C to +125°C"
Y1: library part CMP-0093988-1, "XO (Standard) CMOS Oscillator 1.71V ~ 3.63V Enable/Disable 4-VFLGA", Digikey Part Number=150-DSC6101HA3B-024.0000-ND, Frequency_Fixed=24MHz, Frequency Stability=20ppm, Manufacturer="Microchip Technology", Max Supply Current=3mA, Max Supply Voltage=3.63V, Min Supply Voltage=1.71V, Mouser Part Number=579-6101HA3B-0240000, Operating Temperature Range="-40°C to +125°C"
ZZ1: library part CMP-0077236-1
ZZ2: library part CMP-0077237-1
ZZ3: library part CMP-0077238-1

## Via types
v1: diameter 10, hole 6, TOP to BOTTOM, tented both sides, 154 vias

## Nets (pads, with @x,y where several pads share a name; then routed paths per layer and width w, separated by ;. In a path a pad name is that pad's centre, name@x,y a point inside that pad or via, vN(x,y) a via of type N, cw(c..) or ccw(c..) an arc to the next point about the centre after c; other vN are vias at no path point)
AGND: C10.2 C11.2 C12.2 C13.2 C15.2 C16.2 C17.2 C18.2 C19.2 C21.2 C22.2 C23.2 NT1.2 TP11.1 U2.B6 U2.B7 U2.C10 U2.D4 U2.D5 U2.D6 U2.D7 U2.D8 U2.D10 U2.E4 U2.E5 U2.E6 U2.E7 U2.E8 U2.E10 U2.F3 U2.F4 U2.F5 U2.F6 U2.F7 U2.F8 U2.F10 U2.G3 U2.G4 U2.G5 U2.G6 U2.G7 U2.G8 U2.G10 U2.H3 U2.H4 U2.H5 U2.H6 U2.H7 U2.H8 U2.H10 U2.J3 U2.J4 U2.J5 U2.J6 U2.J7 U2.J8 U2.J9 U2.J10 U2.K3 U2.K8 U2.K10 U2.L3 U2.L4 U2.L5 U2.L6 U2.L7 U2.L8 U2.L9 U2.L10 | length 2285.3
  TOP w5: U2.D10@542.32,555.74 U2.D10@542.32,556.32 ; U2.C10@542.32,581.33 U2.C10@542.67,581.33
  TOP w8: U2.H3@363.19,453.38 v1@375.3,441.3 ; U2.J4@388.78,427.79 v1@376,440.6 ; U2.E4@388.78,530.15 402,543.37 414.37,531 U2.E5@414.37,530.15 ; U2.D4@388.78,555.78 v1(402,569) 402,568.11 U2.D5@414.37,555.74 ; U2.J5@414.37,427.79 414.21,427.79 401.5,440.5 ; U2.H5@414.37,453.38 401.5,440.5 ; U2.J6@439.96,427.79 439.96,427.96 v1(453,441) ; U2.H6@439.96,453.38 440.62,453.38 v1(453,441) ; U2.E6@439.96,530.15 439.96,530.96 v1(453,544) ; U2.D6@439.96,555.74 441.26,555.74 v1(453,544) ; U2.B6@439.96,606.92 441.08,606.92 v1(453,595) 464.92,606.92 U2.B7@465.55,606.92 ; U2.J7@465.55,427.79 465.55,428.45 v1(453,441) ; U2.H7@465.55,453.38 465.38,453.38 v1(453,441) ; U2.E7@465.55,530.15 453,542.7 v1(453,544) ; U2.D7@465.55,555.74 464.74,555.74 v1(453,544) ; U2.D8@491.14,555.74 492.26,555.74 504,544 504,543.01 U2.E8@491.14,530.15 491.14,529.86 504,517 503.58,517 U2.F8@491.14,504.56 503.7,492 504,492 491.14,479.14 U2.G8@491.14,478.97 492.03,478.97 504,467 491.14,454.14 U2.H8@491.14,453.38 491.62,453.38 504,441 ; U2.J9@516.73,427.79 516.73,428.27 504,441 ; U2.K10@542.32,402.2 542.32,401.68 v1(555,389) 542.61,376.61 U2.L10@542.32,376.61 U2.L9@516.73,376.61 516.35,376.61 503.75,364 U2.L8@491.14,376.61 478.35,389.4 ; U2.J10@542.32,427.79 530,440.11 v1(530,441) 542.32,453.32 U2.H10@542.32,453.38 ; U2.G10@542.32,478.97 542.32,479.32 555,492 U2.F10@542.44,504.56 ; U2.F10@542.32,504.56 U2.F10@542.44,504.56 ; U2.D10@542.32,555.74 541.74,555.74 530,544 542.32,531.68 U2.E10@542.32,530.15 542.32,529.68 v1@555,517 ; U2.D10@542.32,556.32 v1(554,568) 555,569 U2.C10@542.67,581.33 ; v1@554.5,516.5 542.56,504.56 U2.F10@542.44,504.56 ; v1@376,440.6 U2.H4@388.78,453.38 401.5,440.66 401.5,440.5 ; v1@376,440.6 U2.J3@363.19,427.79 364.21,427.79 375,417 v1(375,416) 375,415 363.19,403.19 U2.K3@363.19,402.2 U2.L3@363.19,376.61 U2.L4@388.78,376.61 U2.L5@414.37,376.61 U2.L6@439.96,376.61 U2.L7@465.55,376.61 478.35,389.4 ; 478.35,389.4 U2.K8@491.14,402.2 U2.J8@491.14,427.79 504,440.64 504,441
  TOP w12: U2.H3@363.19,453.38 U2.G3@363.19,478.97 U2.F3@363.19,504.56 ; U2.H4@388.78,453.38 U2.G4@388.78,478.97 U2.F4@388.78,504.56 ; U2.H5@414.37,453.38 U2.G5@414.37,478.97 U2.F5@414.37,504.56 ; U2.H6@439.96,453.38 U2.G6@439.96,478.97 U2.F6@439.96,504.56 ; U2.H7@465.55,453.38 U2.G7@465.55,478.97 U2.F7@465.55,504.56
  POWER1 w11: v1(350,416) v1(375,441) ; v1(350,441) v1(375,416)
  POWER1 w12: v1(350,416) v1(375,416) v1(375,441) v1(350,441) v1(350,416)
  GND2 w10: v1(402,544) v1(402,569)
  GND2 w11: v1(350,416) v1(375,441) ; v1(350,441) v1(375,416)
  GND2 w12: v1(350,416) v1(375,416) v1(375,441) v1(350,441) v1(350,416)
  BOTTOM w8: C17.2@433,418 433,421 v1(453,441) ; v1(453,544) 469,544 C16.2@473,548 ; v1(554,568) 554,550 C18.2@555,549 ; C19.2@555,504 v1(555,516)
  BOTTOM w10: TP11.1@817,436 817,458.66
  BOTTOM w12: v1(263,650) 263,633 288,608 C22.2@288,599 ; v1(337,714) 337,697 C23.2@340,694 ; v1(350,416) 350,383.61 C11.2@375,358.61 ; v1(350,441) v1(375,441) 375,482.39 C10.2@378.61,486 C10.2@402,509.39 ; v1(375,416) 375,360.61 376,359.61 C11.2@375,358.61 ; C11.2@375.61,358 C11.2@375,358.61 ; C12.2@510,627 517,620 v1(530,620) ; v1(658,597) 668,597 C15.2@675,590 ; v1(658,640) 668,640 C21.2@675,633
  BOTTOM w20: C13.2@742.77,436 TP11.1@817,436
CLK_IN: R2.2 R3.2 TP2.1 U2.M5 | length 161.7
  TOP w5: v1(414,316) 414,350.64 U2.M5@414.37,351.02
  BOTTOM w5: TP2.1@350,288 355,293 R3.2@415,293 ; v1(414,316) 414,294 R3.2@415,293 ; R2.2@451,293 R3.2@415,293
CSI2_CK_N: J1.25 U2.F2 | length 622
  TOP w5: v1(325.59,518.28) 337.6,506.27 U2.F2@337.6,504.56
  INNER1 w4.5: v1(325.59,518.28) 417.28,518.28 423,524 423,716.14 434.86,728 465.93,728 468.3,728 470.68,730.38 470.68,740.62 473.05,743 477.8,743 480.18,740.62 480.18,730.38 482.55,728 488,728 497,728 504.72,728 510,733.28 510,823 510,825.38 507.62,827.75 497.38,827.75 495,830.12 495,834.88 497.38,837.25 507.62,837.25 510,839.62 510,841 510,846 510,847 510,859.85 v1(504.85,865)
  BOTTOM w5: J1.25@504.21,899.32 504.85,898.69 v1(504.85,865)
CSI2_CK_P: J1.23 U2.F1 | length 621.3
  TOP w5: v1(300,518.28) 312.01,506.27 U2.F1@312.01,504.56
  INNER1 w4.5: v1(300,518.28) 307.91,518.28 320.41,505.78 418.92,505.78 433,519.86 433,712 439,718 508.86,718 509,718.14 520,729.14 520,860.46 v1(524.54,865)
  BOTTOM w5: J1.23@523.9,899.32 524.54,898.69 v1(524.54,865)
CSI2_D0_N: J1.31 U2.E2 | length 622.6
  TOP w5: v1(325.59,543.87) 337.6,531.86 U2.E2@337.6,530.15
  INNER1 w4.5: v1(325.59,543.87) 335.73,543.87 350,558.14 350,640.5 358.93,649.43 376.93,649.43 380,652.5 380,656.36 376.93,659.43 358.93,659.43 350,668.36 350,692.07 358.93,701 376.93,701 380,704.07 380,707.93 376.93,711 358.93,711 350,719.93 350,742.14 367.86,760 385,760 387.38,760 389.75,762.38 389.75,772.62 392.12,775 396.88,775 399.25,772.62 399.25,762.38 401.62,760 406.38,760 408.75,762.38 408.75,772.62 411.12,775 415.88,775 418.25,772.62 418.25,762.38 420.62,760 427,760 433,760 442,760 451,769 451,801.32 v1(446.32,806)
  BOTTOM w5: J1.31@445.16,899.32 445.16,870.7 451.16,864.7 451.16,810.84 v1(446.32,806)
CSI2_D0_P: J1.29 U2.E1 | length 621.3
  TOP w5: v1(300,543.87) 312.01,531.86 U2.E1@312.01,530.15
  INNER1 w4.5: v1(300,543.87) 307.91,543.87 320.41,531.37 337.37,531.37 348.93,542.93 360,554 360,636.36 363.07,639.43 381.07,639.43 390,648.36 390,660.5 381.07,669.43 363.07,669.43 360,672.5 360,687.93 363.07,691 381.07,691 390,699.93 390,712.07 381.07,721 363.07,721 360,724.07 360,738 372,750 446.14,750 461,764.86 461,801 v1(466,806)
  BOTTOM w5: J1.29@464.84,899.32 464.84,870.7 461.16,867.02 461.16,810.84 v1(466,806)
CSI2_D1_N: J1.35 U2.G2 | length 621.9
  TOP w5: v1(325.59,492.69) 325.59,490.98 U2.G2@337.6,478.97
  INNER1 w4.5: v1(325.59,492.69) 317.68,492.69 305.18,480.19 273.81,480.19 240,514 240,737.14 248.93,746.07 338.86,836 406,836 412,842 412,859.31 v1(406.31,865)
  BOTTOM w5: J1.35@405.79,899.32 406.31,898.8 v1(406.31,865)
CSI2_D1_P: J1.33 U2.G1 | length 621.7
  TOP w5: v1(300,492.69) 312.01,480.68 U2.G1@312.01,478.97
  INNER1 w4.5: v1(300,492.69) 275.45,492.69 272.09,496.05 267.06,501.09 267.06,504.44 274.3,511.69 274.3,515.05 270.95,518.41 267.59,518.41 260.34,511.16 256.98,511.16 251.94,516.2 250,518.14 250,519 250,524 250,528.75 250,535.88 252.38,538.25 262.62,538.25 265,540.62 265,545.38 262.62,547.75 252.38,547.75 250,550.12 250,557.25 250,561 250,564 250,733 343,826 410.14,826 419.07,834.93 422,837.86 422,861 v1(426,865)
  BOTTOM w5: J1.33@425.47,899.32 426,898.8 v1(426,865)
CSI2_D2_N: J1.41 U2.D2 | length 622.8
  TOP w5: v1(325.59,569.46) 337.6,557.45 U2.D2@337.6,555.74
  INNER1 w4.5: 281,646 281.43,646 ; 281,656 281.43,656 ; 281,686 281.43,686 ; 281,696 281.43,696 ; v1(325.59,569.46) 317.68,569.46 305.18,556.96 292.9,556.96 275.43,574.43 272.5,577.36 272.5,637.07 281.43,646 ; v1(347.32,806) 352,801.32 352,791.14 296.86,736 282.54,736 275.43,728.89 272.5,725.96 272.5,704.93 281.43,696 ; 281.43,646 318,646 321.07,649.07 321.07,652.93 318,656 281.43,656 ; 281.43,656 272.5,664.93 272.5,677.07 281.43,686 ; 281.43,686 318,686 321.07,689.07 321.07,692.93 318,696 281.43,696
  BOTTOM w5: J1.41@346.73,899.32 346.73,870.7 352.16,865.28 352.16,810.84 v1(347.32,806)
CSI2_D2_P: J1.39 U2.D1 | length 622
  TOP w5: v1(300,569.46) 312.01,557.45 U2.D1@312.01,555.74
  INNER1 w4.5: 282.5,586 282.5,589 282.5,593.75 282.5,600.88 284.88,603.25 295.12,603.25 297.5,605.62 297.5,610.38 295.12,612.75 284.88,612.75 282.5,615.12 282.5,622.25 282.5,624 282.5,632.93 285.57,636 322,636 ; 282.5,587 282.5,581.5 295,569 295.46,569.46 v1(300,569.46) ; 322,666 285.57,666 282.5,669.07 282.5,672.93 285.57,676 322,676 ; 322,706 285.57,706 282.5,709.07 282.5,721.82 286.68,726 301,726 305.5,730.5 308.5,733.5 312.24,737.24 315.6,737.24 322.85,730 326.21,730 329.57,733.36 329.57,736.71 322.32,743.96 322.32,747.32 324,749 362,787 362,801 v1(367,806) ; 322.14,636 331.07,644.93 331.07,657.07 322.14,666 ; 322.14,676 331.07,684.93 331.07,697.07 322.14,706
  BOTTOM w5: J1.39@366.42,899.32 366.42,870.7 362.16,866.44 362.16,810.84 v1(367,806)
CSI2_D3_N: J1.45 U2.H2 | length 620.8
  TOP w5: v1(325.59,467.1) 325.59,465.39 U2.H2@337.6,453.38
  INNER1 w4.5: v1(308,865) 313,860 313,855.14 198,740.14 198,497.86 241.26,454.6 305.18,454.6 317.68,467.1 v1(325.59,467.1)
  BOTTOM w5: J1.45@307.36,899.32 308,898.69 v1(308,865)
CSI2_D3_P: J1.43 U2.H1 | length 622.1
  TOP w5: v1(300,467.1) 312.01,455.09 U2.H1@312.01,453.38
  INNER1 w4.5: v1(300,467.1) 242.9,467.1 208,502 208,582 208,586.75 208,594 208,598.75 208,605.88 210.38,608.25 214.62,608.25 217,610.62 217,615.38 214.62,617.75 210.38,617.75 208,620.12 208,624.88 210.38,627.25 214.62,627.25 217,629.62 217,634.38 214.62,636.75 210.38,636.75 208,639.12 208,643.88 210.38,646.25 214.62,646.25 217,648.62 217,653.38 214.62,655.75 210.38,655.75 208,658.12 208,662.88 210.38,665.25 214.62,665.25 217,667.62 217,672.38 214.62,674.75 210.38,674.75 208,677.12 208,684.25 208,685 208,687 208,736 323,851 323,860.32 v1(327.68,865)
  BOTTOM w5: J1.43@327.05,899.32 327.68,898.69 v1(327.68,865)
